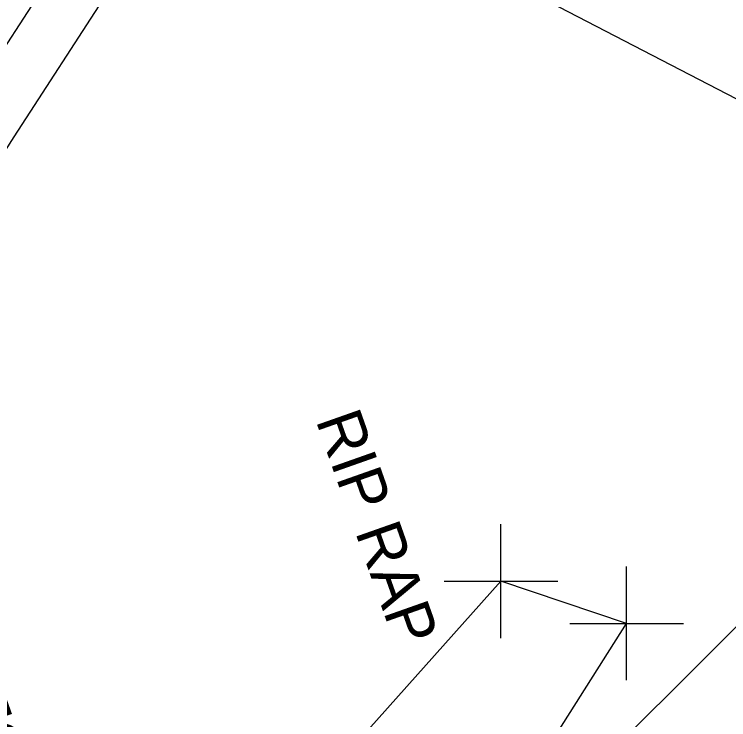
# Model space of a CAD drawing. Extents: x 2004847 to 2009016, y 1134161 to 1140101.
# Drawn here: x 2007991.3 to 2008054.1, y 1139100.8 to 1139162.8 of the extents above; entities that cross this region are included whole.
import ezdxf

# ---------------------------------------------------------------- set-up
doc = ezdxf.new("R2010")
doc.units = 0
for name, color, linetype in [('RD_EX_Conc', 7, 'Continuous'), ('RD_EX_DR_Inlet_txCode', 7, 'Continuous'), ('RD_EX_DV_Prop_txCode', 7, 'Continuous'), ('RD_EX_Fence_ChLk', 7, 'Continuous'), ('RD_EX_Misc', 7, 'Continuous'), ('RD_EX_VEG', 7, 'Continuous'), ('RD_Sketch3', 7, 'Continuous')]:
    doc.layers.add(name, color=color, linetype=linetype)

msp = doc.modelspace()

# ---------------------------------------------------------------- linework, layer by layer
at = {"layer": 'RD_EX_Conc'}
for points in [[(2008012.258, 1139192.316), (2008003.651, 1139179.799), (2007995.336, 1139167.43), (2007987.157, 1139154.821), (2007979.201, 1139142.322), (2007971.095, 1139129.729), (2007962.904, 1139117.197), (2007954.856, 1139104.534), (2007946.938, 1139091.958), (2007939.166, 1139079.213), (2007931.58, 1139066.441), (2007923.915, 1139053.39), (2007916.339, 1139040.676), (2007908.934, 1139027.568), (2007901.347, 1139014.745), (2007894.028, 1139001.836), (2007886.768, 1138988.672), (2007879.687, 1138975.615), (2007872.659, 1138962.368), (2007865.778, 1138949.249), (2007860.038, 1138937.972)], [(2008016.296, 1139189.467), (2008007.766, 1139177.029), (2007999.476, 1139164.697), (2007991.297, 1139152.062), (2007983.392, 1139139.642), (2007975.292, 1139127.057), (2007967.109, 1139114.537), (2007959.059, 1139101.871), (2007951.178, 1139089.355), (2007943.426, 1139076.643), (2007935.879, 1139063.936), (2007928.171, 1139050.827), (2007920.647, 1139038.202), (2007913.233, 1139025.065), (2007905.673, 1139012.288), (2007898.395, 1138999.453), (2007891.121, 1138986.277), (2007884.076, 1138973.288), (2007877.05, 1138960.043), (2007870.213, 1138947.011), (2007864.473, 1138935.734)]]:
    msp.add_lwpolyline(points, dxfattribs=at)
at = {"layer": 'RD_EX_DV_Prop_txCode'}
for p, q in [((2008034.106, 1139108.012), (2008034.106, 1139118.012)), ((2008045.146, 1139104.304), (2008045.146, 1139114.304)), ((2008029.106, 1139113.012), (2008039.106, 1139113.012)), ((2008040.146, 1139109.304), (2008050.146, 1139109.304))]:
    msp.add_line(p, q, dxfattribs=at)
at = {"layer": 'RD_EX_Fence_ChLk'}
msp.add_line((2008056.754, 1139154.381), (2008027.453, 1139169.562), dxfattribs=at)
at = {"layer": 'RD_EX_Misc'}
msp.add_lwpolyline([(2008035.039, 1139093.321), (2008045.146, 1139109.304), (2008034.106, 1139113.012), (2008010.06, 1139086.048), (2008035.039, 1139093.321)], dxfattribs=at)
at = {"layer": 'RD_EX_VEG'}
msp.add_lwpolyline([(2008089.912, 1139119.039), (2008067.011, 1139121.21), (2008041.567, 1139095.826), (2008015.2, 1139074.582), (2008004.962, 1139047.991)], dxfattribs=at)

# ---------------------------------------------------------------- texts
at = {"layer": 'RD_EX_DR_Inlet_txCode'}
for s, p in [("TOP=552.54'", (2007986.323, 1139102.976)), ('BOTTOM OF BOX', (2007981.047, 1139100.903))]:
    msp.add_text(s, height=4.00001, rotation=289.44941, dxfattribs=at).set_placement(p)
at = {"layer": 'RD_Sketch3'}
msp.add_text('RIP RAP', height=4, rotation=289.44941, dxfattribs=at).set_placement((2008017.802, 1139127.169))

doc.saveas('drawing.dxf')
